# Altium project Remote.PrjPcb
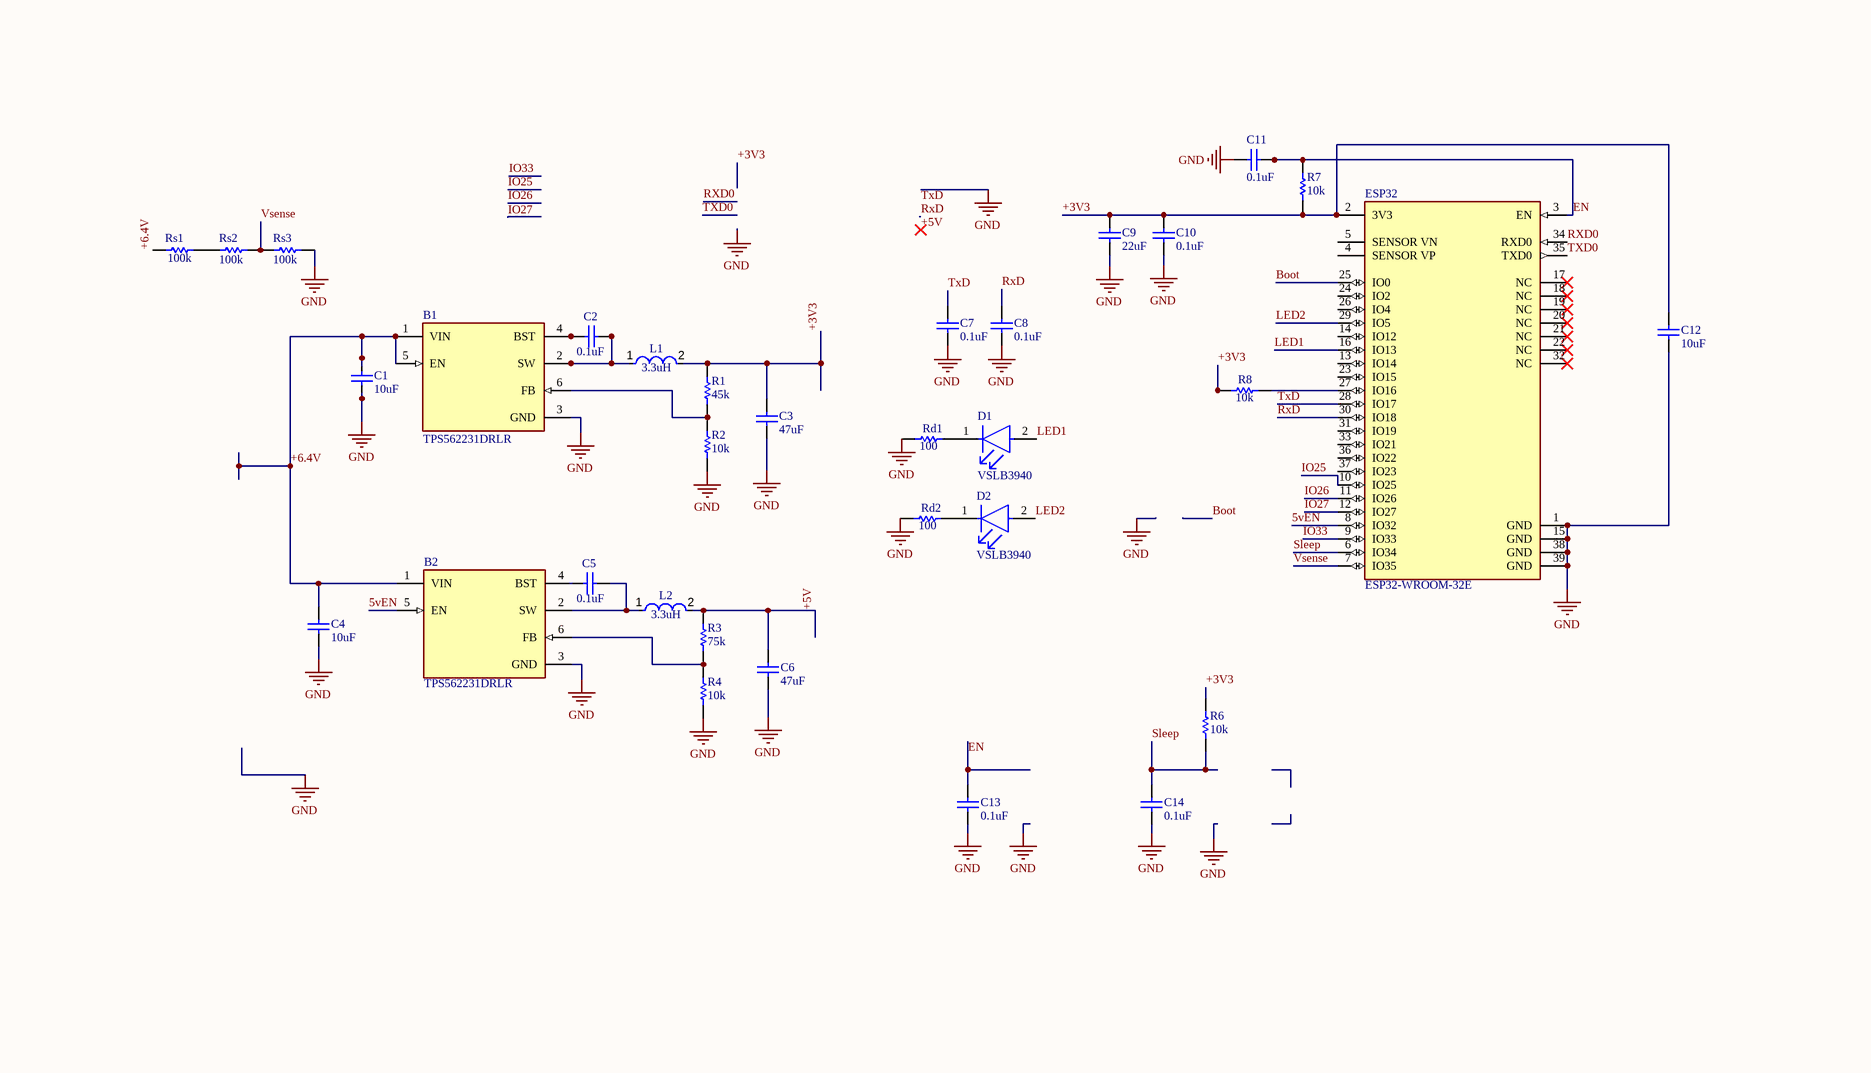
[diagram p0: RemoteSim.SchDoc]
2 sheets, 77 parts. Net scope: global (net labels, ports and power ports of the same name join across sheets).
Board file: Remote.PcbDoc
Sheets:
  RemoteSim.SchDoc
  Remote.SchDoc

## Sheet RemoteSim.SchDoc
size 350 x 199 mm; Organization: ORGANIZATION; Address1: ADDRESS 1; Address2: ADDRESS 2; Address3: ADDRESS 3; Address4: ADDRESS 4; Revision: -; SheetNumber: 1; SheetTotal: 2; ENG_APP_DATE: --/--/--; DSN_APP_DATE: --/--/--; CHK_APP_DATE: --/--/--

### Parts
(Parts that share a designator on the sheet are numbered #1, #2 ... from top to bottom, then left to right.)
B1#1  TPS562231DRLR  [FP-DRL0006A-MFG]
B2#1  TPS562231DRLR  [FP-DRL0006A-MFG]
C1#1  10uF  [CAPC2013X88X50LL20T25]
C2#1  0.1uF  [CAPC2013X88X50LL20T25]
C3#1  47uF  [CAPC2013X88X50LL20T25]
C4#1  10uF  [CAPC2013X88X50LL20T25]
C5#1  0.1uF  [CAPC2013X88X50LL20T25]
C6#1  47uF  [CAPC2013X88X50LL20T25]
C7#1  0.1uF  [CAPC2013X88X50LL20T25]
C8#1  0.1uF  [CAPC2013X88X50LL20T25]
C9#1  22uF  [CAPC2013X88X50LL20T25]
C10#1  0.1uF  [CAPC2013X88X50LL20T25]
C11#1  0.1uF  [CAPC2013X88X50LL20T25]
C12#1  10uF  [CAPC2013X88X50LL20T25]
C13#1  0.1uF  [CAPC2013X88X50LL20T25]
C14#1  0.1uF  [CAPC2013X88X50LL20T25]
D1#1  VSLB3940  [FP-VSLB3940-MFG]
D2#1  VSLB3940  [FP-VSLB3940-MFG]
ESP32#1  ESP32-WROOM-32E  [FP-ESP32-WROOM-32E_M113EH-MFG]
L1#1  3.3uH  [FP-NR4012-MFG]
L2#1  3.3uH  [FP-NR4012-MFG]
R1#1  45k  [RESC2013X60X35ML10T20]
R2#1  10k  [RESC2013X60X35ML10T20]
R3#1  75k  [RESC2013X60X35ML10T20]
R4#1  10k  [RESC2013X60X35ML10T20]
R6#1  10k  [RESC2013X60X35ML10T20]
R7#1  10k  [RESC2013X60X35ML10T20]
R8#1  10k  [RESC2013X60X35ML10T20]
Rd1#1  100  [RESC2013X60X35ML10T20]
Rd2#1  100  [RESC2013X60X35ML10T20]
Rs1#1  100k  [RESC2013X60X35ML10T20]
Rs2#1  100k  [RESC2013X60X35ML10T20]
Rs3#1  100k  [RESC2013X60X35ML10T20]

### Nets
GND: B1#1.3(GND) B2#1.3(GND) C1#1.2 C3#1.2 C4#1.2 C6#1.1 C7#1.2 C8#1.2 C9#1.2 C10#1.2 C11#1.1 C12#1.2 C13#1.2 C14#1.2 ESP32#1.1(GND) ESP32#1.15(GND) ESP32#1.38(GND) ESP32#1.39(GND) R2#1.1 R4#1.1 Rd1#1.2 Rd2#1.2 Rs3#1.1
5vEN: B2#1.5(EN) ESP32#1.8(IO32)
+3V3: C3#1.1 C9#1.1 C10#1.1 C12#1.1 ESP32#1.2(3V3) L1#1.2 R1#1.2 R6#1.2 R7#1.1 R8#1.2
+5V: C6#1.2 L2#1.2 R3#1.2
+6.4V: B1#1.1(VIN) B1#1.5(EN) B2#1.1(VIN) C1#1.1 C4#1.1 Rs1#1.2
Boot: ESP32#1.25(IO0)
EN: C11#1.2 C13#1.1 ESP32#1.3(EN) R7#1.2
IO25: ESP32#1.10(IO25)
IO26: ESP32#1.11(IO26)
IO27: ESP32#1.12(IO27)
IO33: ESP32#1.9(IO33)
LED1: D1#1.2(A) ESP32#1.16(IO13)
LED2: D2#1.2(A) ESP32#1.29(IO5)
RxD: C8#1.1 ESP32#1.30(IO18)
RXD0: ESP32#1.34(RXD0)
Sleep: C14#1.1 ESP32#1.6(IO34) R6#1.1
TxD: C7#1.1 ESP32#1.28(IO17)
TXD0: ESP32#1.35(TXD0)
Vsense: ESP32#1.7(IO35) Rs2#1.1 Rs3#1.2
NetB1#1_2: B1#1.2(SW) C2#1.1 L1#1.1
NetB1#1_4: B1#1.4(BST) C2#1.2
NetB1#1_6: B1#1.6(FB) R1#1.1 R2#1.2
NetB2#1_2: B2#1.2(SW) C5#1.1 L2#1.1
NetB2#1_4: B2#1.4(BST) C5#1.2
NetB2#1_6: B2#1.6(FB) R3#1.1 R4#1.2
NetD1#1_1: D1#1.1(C) Rd1#1.1
NetD2#1_1: D2#1.1(C) Rd2#1.1
NetESP32#1_27: ESP32#1.27(IO16) R8#1.1
NetRs1#1_1: Rs1#1.1 Rs2#1.2

Not connected (* = marked no-connect by the designer): ESP32#1 4(SENSOR_VP) 5(SENSOR_VN) 13(IO14) 14(IO12) 17(NC)* 18(NC)* 19(NC)* 20(NC)* 21(NC)* 22(NC)* 23(IO15) 24(IO2) 26(IO4) 31(IO19) 32(NC)* 33(IO21) 36(IO22) 37(IO23)

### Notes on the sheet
- Labels drawn without touching a wire or pin: +5V, TxD

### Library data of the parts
B1#1 B2#1 = CMP-04918-000372-1: POWER MANAGEMENT
C1#1 C2#1 C3#1 C4#1 C5#1 C6#1 C7#1 C8#1 C9#1 C10#1 C11#1 C12#1 C13#1 C14#1 = CMP-2007-00266-1: Manufacturer: Kemet; Part Number: C0805C103K5RACTU
D1#1 D2#1 = CMP-00030-18785862-1: VSLB3940 940 nm 100 mA ±22° Through Hole High Speed Infrared Emitting Diode - T-1; Power Rating: 160mW; Rise Time: 15ns; Peak Wavelength: 940nm; Lens Style: Circular, Diffused, Round; Reverse Voltage: 5V; Viewing Angle: 44°; Forward Current: 100mA; Number of Elements: 1; Forward Voltage: 1.35V
ESP32#1 = CMP-194065-000012-1: RX TXRX MOD WIFI TRACE ANT SMD
L1#1 L2#1 = CMP-14484-001001-1: SMD Power Inductors 3.3uH ±20% 1.4A 84mΩ; Self Resonant Frequency: 60MHz; Max DC Current: 1.7A; DC Resistance (DCR): 84mR; Test Frequency: 100kHz; Core Material: Ferrite; Shielding: Shielded
R1#1 R2#1 R3#1 R4#1 R6#1 R7#1 R8#1 Rd1#1 Rd2#1 Rs1#1 Rs2#1 Rs3#1 = CMP-2100-03671-1: Chip Resistor, 1 KOhm, +/- 1%, 125 mW, -55 to 155 degC, 0805 (2012 Metric), RoHS, Tape and Reel; Manufacturer: Yageo; Temperature Coefficient: 100ppm/degreesC; Voltage Rating (DC): 150V; Max Power Dissipation: 125mW; Resistance: 1KOhm; Value: 1KOhm

## Sheet Remote.SchDoc
size 350 x 199 mm; Organization: ORGANIZATION; Address1: ADDRESS 1; Address2: ADDRESS 2; Address3: ADDRESS 3; Address4: ADDRESS 4; Revision: -; SheetNumber: 1; SheetTotal: 1; ENG_APP_DATE: --/--/--; DSN_APP_DATE: --/--/--; CHK_APP_DATE: --/--/--
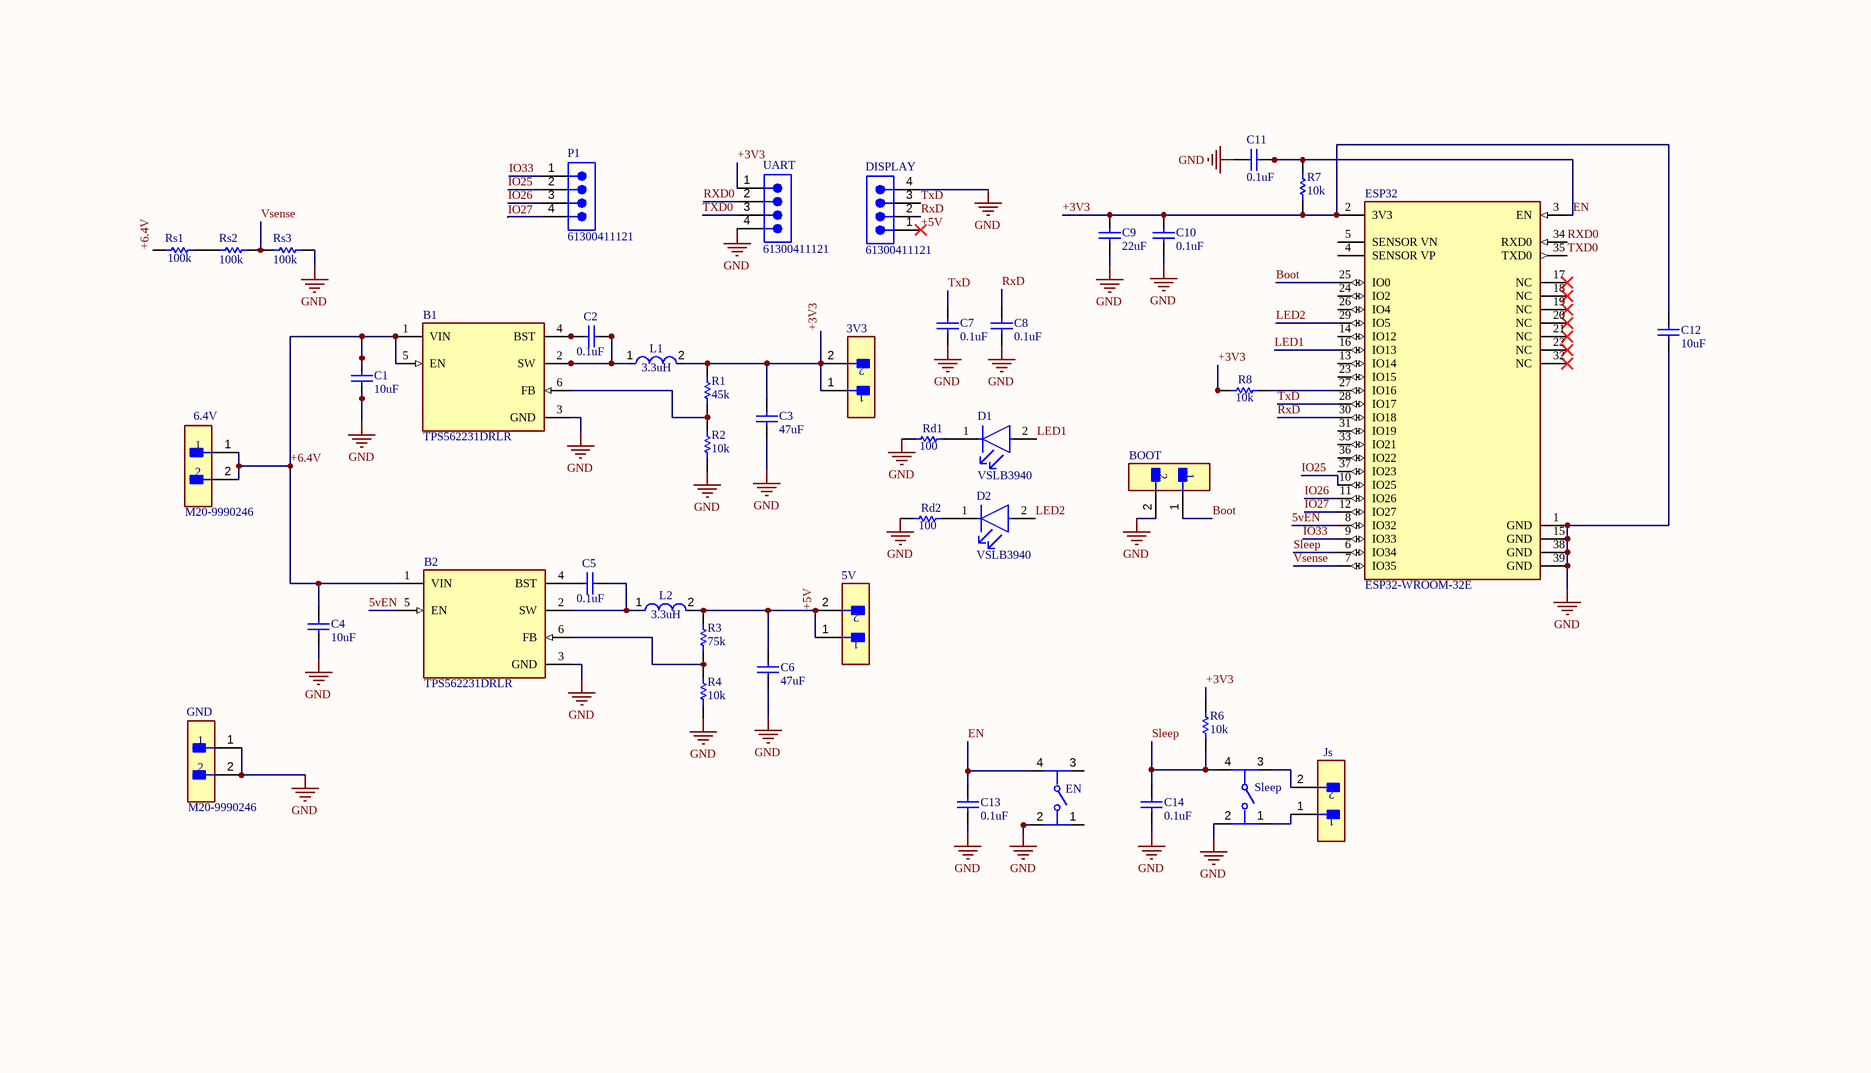
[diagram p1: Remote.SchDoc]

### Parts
(Parts that share a designator on the sheet are numbered #1, #2 ... from top to bottom, then left to right.)
3V3  M20-9990246  [FP-M20-9990246-MFG]  (value not drawn)
5V  M20-9990246  [FP-M20-9990246-MFG]  (value not drawn)
6.4V  M20-9990246  [FP-M20-9990246-MFG]
B1#2  TPS562231DRLR  [FP-DRL0006A-MFG]
B2#2  TPS562231DRLR  [FP-DRL0006A-MFG]
BOOT  M20-9990246  [FP-M20-9990246-MFG]  (value not drawn)
C1#2  10uF  [CAPC2013X88X50LL20T25]
C2#2  0.1uF  [CAPC2013X88X50LL20T25]
C3#2  47uF  [CAPC2013X88X50LL20T25]
C4#2  10uF  [CAPC2013X88X50LL20T25]
C5#2  0.1uF  [CAPC2013X88X50LL20T25]
C6#2  47uF  [CAPC2013X88X50LL20T25]
C7#2  0.1uF  [CAPC2013X88X50LL20T25]
C8#2  0.1uF  [CAPC2013X88X50LL20T25]
C9#2  22uF  [CAPC2013X88X50LL20T25]
C10#2  0.1uF  [CAPC2013X88X50LL20T25]
C11#2  0.1uF  [CAPC2013X88X50LL20T25]
C12#2  10uF  [CAPC2013X88X50LL20T25]
C13#2  0.1uF  [CAPC2013X88X50LL20T25]
C14#2  0.1uF  [CAPC2013X88X50LL20T25]
D1#2  VSLB3940  [FP-VSLB3940-MFG]
D2#2  VSLB3940  [FP-VSLB3940-MFG]
DISPLAY  61300411121  [61300411121]
EN  PTS647SK38SMTR2LFS  [FP-PTS647SK38SMTR2LFS-MFG]  (value not drawn)
ESP32#2  ESP32-WROOM-32E  [FP-ESP32-WROOM-32E_M113EH-MFG]
GND  M20-9990246  [FP-M20-9990246-MFG]
Js  M20-9990246  [FP-M20-9990246-MFG]  (value not drawn)
L1#2  3.3uH  [FP-NR4012-MFG]
L2#2  3.3uH  [FP-NR4012-MFG]
P1  61300411121  [61300411121]
R1#2  45k  [RESC2013X60X35ML10T20]
R2#2  10k  [RESC2013X60X35ML10T20]
R3#2  75k  [RESC2013X60X35ML10T20]
R4#2  10k  [RESC2013X60X35ML10T20]
R6#2  10k  [RESC2013X60X35ML10T20]
R7#2  10k  [RESC2013X60X35ML10T20]
R8#2  10k  [RESC2013X60X35ML10T20]
Rd1#2  100  [RESC2013X60X35ML10T20]
Rd2#2  100  [RESC2013X60X35ML10T20]
Rs1#2  100k  [RESC2013X60X35ML10T20]
Rs2#2  100k  [RESC2013X60X35ML10T20]
Rs3#2  100k  [RESC2013X60X35ML10T20]
Sleep  PTS647SK38SMTR2LFS  [FP-PTS647SK38SMTR2LFS-MFG]  (value not drawn)
UART  61300411121  [61300411121]

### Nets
GND: B1#2.3(GND) B2#2.3(GND) BOOT.2 C1#2.2 C3#2.2 C4#2.2 C6#2.1 C7#2.2 C8#2.2 C9#2.2 C10#2.2 C11#2.1 C12#2.2 C13#2.2 C14#2.2 DISPLAY.4 EN.2 ESP32#2.1(GND) ESP32#2.15(GND) ESP32#2.38(GND) ESP32#2.39(GND) GND.1 GND.2 R2#2.1 R4#2.1 Rd1#2.2 Rd2#2.2 Rs3#2.1 Sleep.2 UART.4
5vEN: B2#2.5(EN) ESP32#2.8(IO32)
+3V3: 3V3.1 3V3.2 C3#2.1 C9#2.1 C10#2.1 C12#2.1 ESP32#2.2(3V3) L1#2.2 R1#2.2 R6#2.2 R7#2.1 R8#2.2 UART.1
+5V: 5V.1 5V.2 C6#2.2 DISPLAY.1 L2#2.2 R3#2.2
+6.4V: 6.4V.1 6.4V.2 B1#2.1(VIN) B1#2.5(EN) B2#2.1(VIN) C1#2.1 C4#2.1 Rs1#2.2
Boot: BOOT.1 ESP32#2.25(IO0)
EN: C11#2.2 C13#2.1 EN.4 ESP32#2.3(EN) R7#2.2
IO25: ESP32#2.10(IO25) P1.2
IO26: ESP32#2.11(IO26) P1.3
IO27: ESP32#2.12(IO27) P1.4
IO33: ESP32#2.9(IO33) P1.1
LED1: D1#2.2(A) ESP32#2.16(IO13)
LED2: D2#2.2(A) ESP32#2.29(IO5)
RxD: C8#2.1 DISPLAY.2 ESP32#2.30(IO18)
RXD0: ESP32#2.34(RXD0) UART.2
Sleep: C14#2.1 ESP32#2.6(IO34) R6#2.1 Sleep.4
TxD: C7#2.1 DISPLAY.3 ESP32#2.28(IO17)
TXD0: ESP32#2.35(TXD0) UART.3
Vsense: ESP32#2.7(IO35) Rs2#2.1 Rs3#2.2
NetB1#2_2: B1#2.2(SW) C2#2.1 L1#2.1
NetB1#2_4: B1#2.4(BST) C2#2.2
NetB1#2_6: B1#2.6(FB) R1#2.1 R2#2.2
NetB2#2_2: B2#2.2(SW) C5#2.1 L2#2.1
NetB2#2_4: B2#2.4(BST) C5#2.2
NetB2#2_6: B2#2.6(FB) R3#2.1 R4#2.2
NetD1#2_1: D1#2.1(C) Rd1#2.1
NetD2#2_1: D2#2.1(C) Rd2#2.1
NetESP32#2_27: ESP32#2.27(IO16) R8#2.1
NetJs_1: Js.1 Sleep.1
NetJs_2: Js.2 Sleep.3
NetRs1#2_1: Rs1#2.1 Rs2#2.2

Not connected (* = marked no-connect by the designer): EN 1 3; ESP32#2 4(SENSOR_VP) 5(SENSOR_VN) 13(IO14) 14(IO12) 17(NC)* 18(NC)* 19(NC)* 20(NC)* 21(NC)* 22(NC)* 23(IO15) 24(IO2) 26(IO4) 31(IO19) 32(NC)* 33(IO21) 36(IO22) 37(IO23)

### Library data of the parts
3V3 5V 6.4V BOOT GND Js = CMP-15831-000009-1: CONN HEADER VERT 2POS 2.54MM; Manufacturer: Harwin; Conn Gender: Male; Conn Orientation: Vertical; Number Of Contacts: 2; Current Rating: 3A
B1#2 B2#2 = CMP-04918-000372-1: POWER MANAGEMENT
C1#2 C2#2 C3#2 C4#2 C5#2 C6#2 C7#2 C8#2 C9#2 C10#2 C11#2 C12#2 C13#2 C14#2 = CMP-2007-00266-1: as C1#1 on sheet RemoteSim
D1#2 D2#2 = CMP-00030-18785862-1: as D1#1 on sheet RemoteSim
DISPLAY P1 UART = CMP-1502-01064-3: NexarPartId: 32855522; Operating Supply Voltage: 250V; Pitch: 2.54mm; Contact Resistance: 20mΩ; Number of Positions: 4; Current Rating: 3A; Connector Type: Male Pin; Gender: Male
EN Sleep = CMP-10040-000033-1: TACT 4.5 X 4.5, 3.8 MM H, 2.5N,; Switch Function: Off-Mom; Switch Travel: 0.25mm; Actuator Type: Standard; Illumination Type: Non-Illuminated; Mechanical Life: 100000Cycles; Ratings: IP40; Operating Force: 250gf; Throw Configuration: SPST
ESP32#2 = CMP-194065-000012-1: RX TXRX MOD WIFI TRACE ANT SMD
L1#2 L2#2 = CMP-14484-001001-1: as L1#1 on sheet RemoteSim
R1#2 R2#2 R3#2 R4#2 R6#2 R7#2 R8#2 Rd1#2 Rd2#2 Rs1#2 Rs2#2 Rs3#2 = CMP-2100-03671-1: as R1#1 on sheet RemoteSim

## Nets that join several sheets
GND: RemoteSim (23 pins), Remote (30 pins)
5vEN: RemoteSim (B2#1.5 ESP32#1.8), Remote (B2#2.5 ESP32#2.8)
+3V3: RemoteSim (10 pins), Remote (13 pins)
+5V: RemoteSim (C6#1.2 L2#1.2 R3#1.2), Remote (6 pins)
+6.4V: RemoteSim (6 pins), Remote (8 pins)
Boot: RemoteSim (ESP32#1.25), Remote (BOOT.1 ESP32#2.25)
EN: RemoteSim (C11#1.2 C13#1.1 ESP32#1.3 R7#1.2), Remote (5 pins)
IO25: RemoteSim (ESP32#1.10), Remote (ESP32#2.10 P1.2)
IO26: RemoteSim (ESP32#1.11), Remote (ESP32#2.11 P1.3)
IO27: RemoteSim (ESP32#1.12), Remote (ESP32#2.12 P1.4)
IO33: RemoteSim (ESP32#1.9), Remote (ESP32#2.9 P1.1)
LED1: RemoteSim (D1#1.2 ESP32#1.16), Remote (D1#2.2 ESP32#2.16)
LED2: RemoteSim (D2#1.2 ESP32#1.29), Remote (D2#2.2 ESP32#2.29)
RxD: RemoteSim (C8#1.1 ESP32#1.30), Remote (C8#2.1 DISPLAY.2 ESP32#2.30)
RXD0: RemoteSim (ESP32#1.34), Remote (ESP32#2.34 UART.2)
Sleep: RemoteSim (C14#1.1 ESP32#1.6 R6#1.1), Remote (C14#2.1 ESP32#2.6 R6#2.1 Sleep.4)
TxD: RemoteSim (C7#1.1 ESP32#1.28), Remote (C7#2.1 DISPLAY.3 ESP32#2.28)
TXD0: RemoteSim (ESP32#1.35), Remote (ESP32#2.35 UART.3)
Vsense: RemoteSim (ESP32#1.7 Rs2#1.1 Rs3#1.2), Remote (ESP32#2.7 Rs2#2.1 Rs3#2.2)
